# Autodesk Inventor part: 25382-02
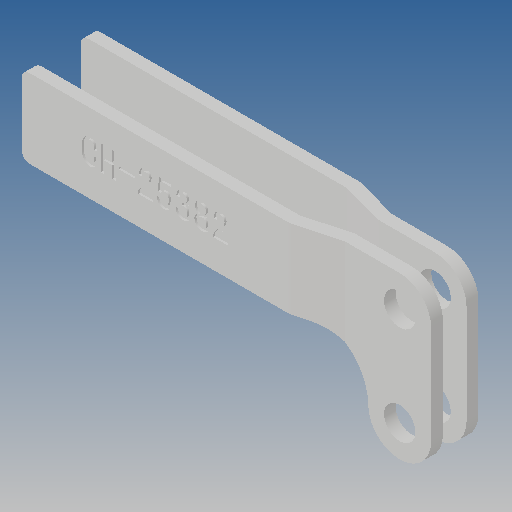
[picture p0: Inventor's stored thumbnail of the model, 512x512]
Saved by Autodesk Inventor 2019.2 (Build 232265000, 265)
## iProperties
Created: 2012-09
Part Number: 25382-02
Material: Ogólny
Document SubType Name: Modeling
Designer: CADENGINEERING4
Density: 1 g/cm^3
Appearance: Domyślna
Author: CADENGINEERING4
Revision Number: ÈÎºÎ
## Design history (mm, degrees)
feature "ÇÐ³ý-À­Éì3"
feature "ÇÐ³ý-À­Éì5"
node "Bryła1"
node "Bryła2"
